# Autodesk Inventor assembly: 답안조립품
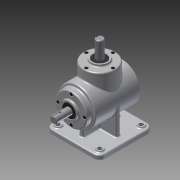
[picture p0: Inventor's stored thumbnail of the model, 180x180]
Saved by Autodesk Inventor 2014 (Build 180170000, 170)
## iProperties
Created: 2015-07
Part Number: 답안조립품
Document SubType Name: Assembly
Designer: 704_05
Author: 704_05
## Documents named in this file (14)
- C:\Users\704_05\Desktop\450705V1005\답안조립품.iam
- C:\Users\704_05\Desktop\450705V1005\본체.ipt
- C:\Users\704_05\Desktop\450705V1005\M4.ipt
- C:\Users\704_05\Desktop\450705V1005\메인 베벨기어.ipt
- C:\Users\704_05\Desktop\450705V1005\메인 축.ipt
- 메인 축.ipt
- C:\Users\704_05\Desktop\450705V1005\베어링 6203.ipt
- C:\Users\704_05\Desktop\450705V1005\서브 베벨기어.ipt
- C:\Users\704_05\Desktop\450705V1005\서브 축.ipt
- 서브 축.ipt
- C:\Users\704_05\Desktop\450705V1005\오일실.ipt
- C:\Users\704_05\Desktop\450705V1005\커버.ipt
- C:\Users\704_05\Desktop\450705V1005\키 4x4.ipt
- C:\Users\704_05\Desktop\450705V1005\키 5x5.ipt
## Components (8 placed, 1 different names)
1. M4:1 — 각도:5
2. M4:2 — 각도:3
3. M4:3 — 각도:11
4. M4:4 — 각도:12
5. M4:5 — 각도:6
6. M4:6 — 각도:4
7. M4:7 — 각도:9
8. M4:8 — 각도:10
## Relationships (8: Angle 8)
- 각도:3 [Angle]: M4:2
- 각도:4 [Angle]: M4:6
- 각도:5 [Angle]: M4:1
- 각도:6 [Angle]: M4:5
- 각도:9 [Angle]: M4:7
- 각도:10 [Angle]: M4:8
- 각도:11 [Angle]: M4:3
- 각도:12 [Angle]: M4:4
